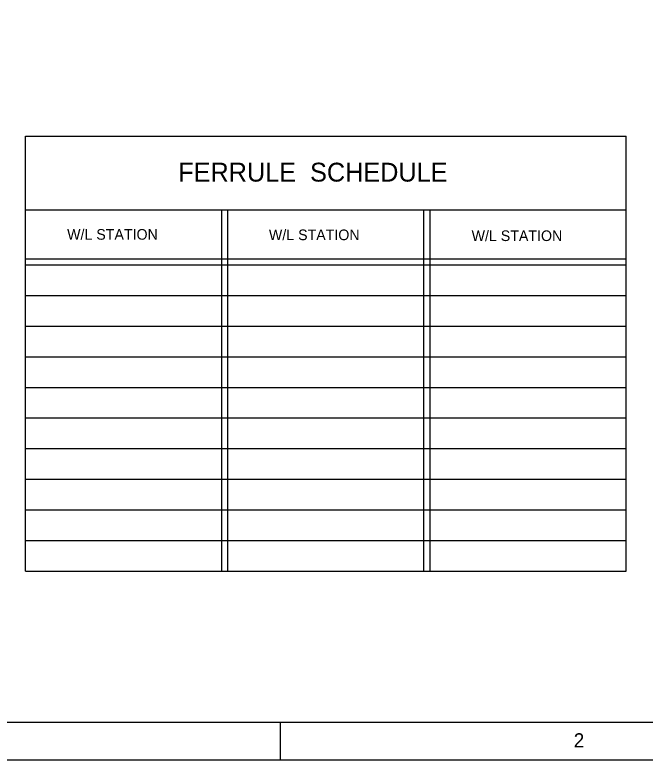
# Model space of a CAD drawing. Extents: x 44742.55 to 44745.38, y 44738.95 to 44741.13.
# Drawn here: x 44742.927 to 44743.462, y 44738.947 to 44739.581 of the extents above; entities that cross this region are included whole.
import ezdxf

# ---------------------------------------------------------------- set-up
doc = ezdxf.new("R2010")
doc.units = 0
for name, color, linetype in [('Level 1', 7, 'Continuous'), ('Level 10', 7, 'Continuous'), ('Level 3', 7, 'Continuous'), ('Level 4', 7, 'Continuous'), ('Level 9', 7, 'Continuous'), ('S-GRID-HORZ', 7, 'Continuous'), ('S-GRID-VERT', 7, 'Continuous')]:
    doc.layers.add(name, color=color, linetype=linetype)

msp = doc.modelspace()

# ---------------------------------------------------------------- linework, layer by layer
at = {"layer": 'Level 1'}
msp.add_lwpolyline([(44742.55302, 44741.13232), (44745.38041, 44741.13232), (44745.38041, 44738.94702), (44742.55302, 44738.94702)], close=True, dxfattribs=at)
at = {"layer": 'Level 10'}
for p, q in [((44742.93595, 44739.47748), (44743.44635, 44739.47748)), ((44742.93595, 44739.1077), (44742.93595, 44739.47748)), ((44743.44635, 44739.1077), (44743.44635, 44739.47748)), ((44742.93595, 44739.41498), (44743.44635, 44739.41498)), ((44742.93595, 44739.1077), (44743.44635, 44739.1077)), ((44743.1527, 44738.94702), (44743.1527, 44738.97941))]:
    msp.add_line(p, q, dxfattribs=at)
at = {"layer": 'Level 9'}
msp.add_line((44742.64941, 44738.97941), (44745.17144, 44738.97941), dxfattribs=at)
at = {"layer": 'S-GRID-HORZ'}
for p, q in [((44742.93595, 44739.37332), (44743.44635, 44739.37332)), ((44742.93595, 44739.36811), (44743.44635, 44739.36811)), ((44742.93595, 44739.34207), (44743.44635, 44739.34207)), ((44742.93595, 44739.31602), (44743.44635, 44739.31602)), ((44742.93595, 44739.28998), (44743.44635, 44739.28998)), ((44742.93595, 44739.26395), (44743.44635, 44739.26395)), ((44742.93595, 44739.23791), (44743.44635, 44739.23791)), ((44742.93595, 44739.21187), (44743.44635, 44739.21187)), ((44742.93595, 44739.18583), (44743.44635, 44739.18583)), ((44742.93595, 44739.15979), (44743.44635, 44739.15979)), ((44742.93595, 44739.13374), (44743.44635, 44739.13374))]:
    msp.add_line(p, q, dxfattribs=at)
at = {"layer": 'S-GRID-VERT'}
for p, q in [((44743.10261, 44739.1077), (44743.10261, 44739.41498)), ((44743.10782, 44739.1077), (44743.10782, 44739.41498)), ((44743.27447, 44739.1077), (44743.27447, 44739.41498)), ((44743.27968, 44739.1077), (44743.27968, 44739.41498))]:
    msp.add_line(p, q, dxfattribs=at)

# ---------------------------------------------------------------- texts
at = {"layer": 'Level 1'}
msp.add_text('2', height=0.01203, dxfattribs=at).set_placement((44743.40177, 44738.95782))
at = {"layer": 'Level 3'}
msp.add_text('FERRULE  SCHEDULE', height=0.0160405, dxfattribs=at).set_placement((44743.06566, 44739.43889))
at = {"layer": 'Level 4'}
for p in [(44742.97124, 44739.38948), (44743.14273, 44739.38911), (44743.31498, 44739.38835)]:
    msp.add_text('W/L STATION', height=0.0090203, dxfattribs=at).set_placement(p)

doc.saveas('drawing.dxf')
